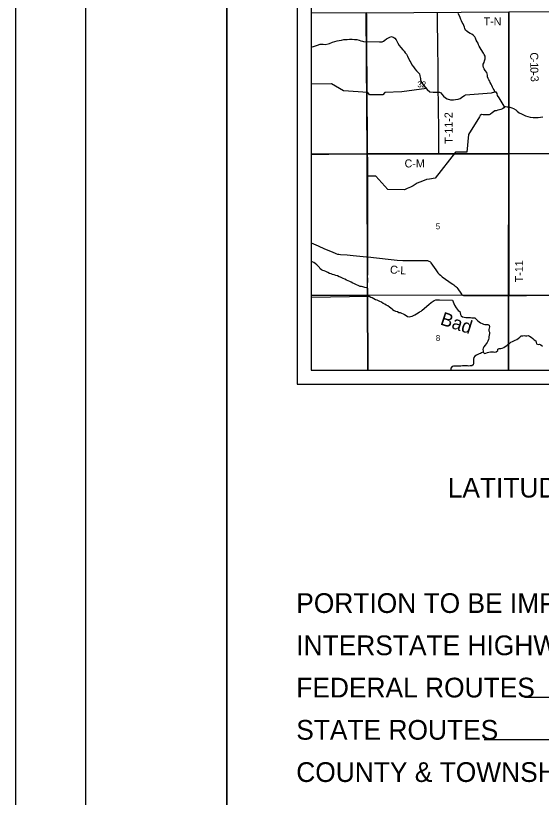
# Model space of a CAD drawing. Extents: x 0 to 34, y 0 to 22.
# Drawn here: x 0 to 3.74, y 11.07 to 16.62 of the extents above; entities that cross this region are included whole.
import ezdxf

# ---------------------------------------------------------------- set-up
doc = ezdxf.new("R2010")
doc.units = 0
for name, color, linetype in [('Default', 7, 'Continuous'), ('GM_X_County_Road', 7, 'Continuous'), ('GM_X_County_Road_Text', 7, 'Continuous'), ('GM_X_Minor_River', 7, 'Continuous'), ('GM_X_Minor_River_Text', 7, 'Continuous'), ('GM_X_Section', 7, 'Continuous'), ('GM_X_Section_Text', 7, 'Continuous'), ('GM_X_Township_Road', 7, 'Continuous'), ('GM_X_Township_Road_Text', 7, 'Continuous'), ('SH_Border', 7, 'Continuous'), ('SH_Cut_Line', 7, 'Continuous'), ('SH_Data', 7, 'Continuous'), ('SH_Text', 7, 'Continuous')]:
    doc.layers.add(name, color=color, linetype=linetype)

msp = doc.modelspace()

# ---------------------------------------------------------------- linework, layer by layer
at = {"layer": 'Default'}
for points in [[(2.1, 16.6364), (2.1, 15.6339), (2.4995, 15.6374), (2.4922, 16.6384)], [(2.1, 15.6339), (2.1, 14.6306), (2.5018, 14.6334), (2.4995, 15.6374)], [(2.1, 14.6306), (2.1, 14.1), (2.5043, 14.1), (2.5018, 14.6334)], [(2.5043, 14.1), (3.5024, 14.1), (3.5022, 14.6297), (2.5018, 14.6334)], [(3.5024, 14.1), (4.5087, 14.1), (4.5085, 14.6335), (3.5022, 14.6297)]]:
    msp.add_lwpolyline(points, close=True, dxfattribs=at)
msp.add_lwpolyline([(2.1, 16.6348), (2.1, 14.1), (7.5225, 14.1), (7.5244, 14.8701), (7.5216, 15.6399), (7.5206, 15.6813), (7.5192, 15.8554), (7.5184, 15.927), (7.5171, 16.0545), (7.5165, 16.1851), (7.5145, 16.4463), (7.5138, 16.5271), (7.5134, 16.6254)], dxfattribs=at)
at = {"layer": 'GM_X_County_Road'}
for points in [[(2.5018, 15.6365), (2.5014, 15.6639), (2.501, 15.7044), (2.501, 15.7417), (2.5006, 15.8101), (2.4991, 15.9935), (2.4985, 16.1303), (2.4979, 16.1769), (2.4966, 16.3417), (2.4965, 16.4039), (2.4959, 16.4629), (2.4958, 16.5096), (2.4953, 16.5562), (2.495, 16.6277), (2.4948, 16.6366)], [(2.1, 15.6332), (2.1688, 15.6336), (2.2248, 15.6343), (2.3211, 15.6353), (2.433, 15.6357), (2.4828, 15.636), (2.5018, 15.6365)], [(2.5018, 15.6365), (2.517, 15.6369), (2.6538, 15.6376), (2.6911, 15.6376), (2.8621, 15.6383), (3.0086, 15.639)], [(2.5029, 14.9045), (2.503, 14.9093), (2.5029, 14.9373), (2.503, 15.0526), (2.5029, 15.0985), (2.5029, 15.195), (2.5033, 15.2482), (2.5032, 15.294), (2.5032, 15.3313), (2.5032, 15.4494), (2.5029, 15.4992), (2.5029, 15.5209), (2.5024, 15.5956), (2.5018, 15.6329), (2.5018, 15.6365)], [(3.0086, 15.639), (3.0206, 15.639), (3.0952, 15.6389), (3.2383, 15.6388), (3.316, 15.6383), (3.3253, 15.6385), (3.3284, 15.6389), (3.3564, 15.639), (3.5073, 15.6383)], [(3.5073, 15.6383), (3.515, 15.6382), (3.5989, 15.6388), (3.6297, 15.6388), (3.6794, 15.639), (3.7261, 15.639), (3.7634, 15.6393), (3.8007, 15.6393), (3.8287, 15.6395), (3.8908, 15.6397), (3.9188, 15.6396), (3.9655, 15.6399), (4.0059, 15.6398), (4.0081, 15.6399)], [(2.1, 15.0042), (2.1494, 14.9828), (2.1951, 14.9631), (2.2493, 14.9397), (2.2752, 14.9288), (2.2871, 14.9249), (2.2962, 14.9229), (2.3086, 14.9213), (2.3551, 14.9185), (2.3983, 14.9157), (2.4941, 14.9055), (2.5029, 14.9045)], [(2.505, 14.1), (2.505, 14.1041), (2.5049, 14.1259), (2.5049, 14.1756), (2.5043, 14.2471), (2.5042, 14.3), (2.5039, 14.3124), (2.5036, 14.3279), (2.5039, 14.359), (2.5039, 14.3715), (2.503, 14.3905), (2.5025, 14.5109), (2.5016, 14.586), (2.5016, 14.6637), (2.5016, 14.6888), (2.5023, 14.7507), (2.5019, 14.7634), (2.5021, 14.7853), (2.5021, 14.8502), (2.5023, 14.8751), (2.5029, 14.9045)], [(2.5029, 14.9045), (2.6486, 14.8884), (2.7105, 14.8821), (2.7508, 14.879), (2.7757, 14.8784), (2.8303, 14.8792), (2.917, 14.8794), (2.9262, 14.8787), (2.9321, 14.8774), (2.9377, 14.875), (2.9428, 14.8719), (2.9474, 14.8679), (2.9514, 14.8633), (2.987, 14.8124), (3.0017, 14.7923), (3.0099, 14.7828), (3.0189, 14.7741), (3.031, 14.7643), (3.1019, 14.7144), (3.1067, 14.7102), (3.1141, 14.7052), (3.1214, 14.7002), (3.1284, 14.6942), (3.1348, 14.6875), (3.1423, 14.6777), (3.1631, 14.6467), (3.1691, 14.6394), (3.174, 14.6353), (3.1768, 14.6337), (3.1797, 14.6324), (3.1829, 14.6316), (3.1892, 14.6309), (3.2328, 14.6312), (3.3197, 14.6312), (3.4595, 14.6303), (3.493, 14.6304), (3.5083, 14.6304)], [(3.5083, 14.6304), (3.5237, 14.6305), (3.531, 14.6306), (3.6305, 14.6314), (3.9195, 14.634), (3.9471, 14.6339)]]:
    msp.add_lwpolyline(points, dxfattribs=at)
at = {"layer": 'GM_X_Minor_River'}
msp.add_line((2.1, 14.6182), (2.5092, 14.6252), dxfattribs=at)
for points in [[(3.4059, 16.0777), (3.3999, 16.0902), (3.3944, 16.1002), (3.3895, 16.1108), (3.3844, 16.1219), (3.3792, 16.1322), (3.3728, 16.1421), (3.3692, 16.1516), (3.3625, 16.1619), (3.3576, 16.1715), (3.354, 16.1829), (3.353, 16.1939), (3.3508, 16.2042), (3.3482, 16.2137), (3.3378, 16.2282), (3.3288, 16.2401), (3.3248, 16.2504), (3.3226, 16.2618), (3.3239, 16.2731), (3.3293, 16.2856), (3.3329, 16.2977), (3.3372, 16.3098), (3.3365, 16.3193), (3.3367, 16.3292), (3.3292, 16.3421), (3.324, 16.3524), (3.3084, 16.3769), (3.3017, 16.3891), (3.2954, 16.3998), (3.2891, 16.4108), (3.2861, 16.4219), (3.2798, 16.4322), (3.2727, 16.444), (3.2672, 16.4566), (3.2643, 16.4669), (3.2515, 16.4784), (3.2418, 16.4872), (3.2308, 16.4915), (3.2191, 16.4973), (3.2082, 16.5054), (3.1977, 16.515), (3.1918, 16.5253), (3.19, 16.5351), (3.1856, 16.5473), (3.1808, 16.5584), (3.1741, 16.5698), (3.1697, 16.5809), (3.1641, 16.5908), (3.156, 16.6118), (3.1456, 16.6323)], [(2.1, 16.3947), (2.116, 16.3985), (2.1449, 16.4089), (2.1644, 16.4163), (2.1852, 16.4149), (2.2007, 16.4129), (2.2209, 16.4168), (2.2315, 16.4201), (2.2521, 16.4291), (2.2688, 16.4334), (2.2844, 16.4378), (2.3003, 16.4403), (2.3163, 16.4447), (2.3334, 16.4472), (2.3554, 16.4493), (2.3732, 16.4506), (2.3911, 16.4508), (2.4092, 16.4487), (2.4248, 16.4475), (2.441, 16.4439), (2.4524, 16.4392), (2.4641, 16.4368), (2.472, 16.4329), (2.5861, 16.4322), (2.6039, 16.4324), (2.615, 16.4368), (2.6234, 16.4428), (2.636, 16.4526), (2.6501, 16.4604), (2.6592, 16.4652), (2.6707, 16.4693), (2.6873, 16.4631), (2.6944, 16.4566), (2.7034, 16.4451), (2.7164, 16.4226), (2.7264, 16.4065), (2.7376, 16.3909), (2.7515, 16.3752), (2.7605, 16.3648), (2.7679, 16.3541), (2.7784, 16.3442), (2.7847, 16.3308), (2.8021, 16.2954), (2.8085, 16.2854), (2.8166, 16.2694), (2.8271, 16.2537), (2.8364, 16.2404), (2.8495, 16.2262), (2.8619, 16.2151), (2.8693, 16.2036), (2.8738, 16.1907), (2.8777, 16.1713), (2.878, 16.1618), (2.8828, 16.1496), (2.8872, 16.1393), (2.9257, 16.0926), (2.9434, 16.0773), (2.9668, 16.0744), (2.9763, 16.0743), (2.9896, 16.0746), (3.0017, 16.0737), (3.0116, 16.0732), (3.0221, 16.0701), (3.0296, 16.0601), (3.0408, 16.0463), (3.054, 16.0341), (3.0664, 16.0264), (3.0913, 16.0204), (3.1122, 16.0202)], [(2.92, 16.0996), (2.7447, 16.0762), (2.6245, 16.0721), (2.6106, 16.0548), (2.5159, 16.0557), (2.502, 16.0725), (2.3297, 16.0837), (2.2457, 16.1328), (2.1, 16.1315)], [(3.1122, 16.0202), (3.1258, 16.0227), (3.1445, 16.0252), (3.1589, 16.0289), (3.1788, 16.0438), (3.1891, 16.0498), (3.1948, 16.0532), (3.1979, 16.0543), (3.383, 16.0699), (3.4059, 16.0777), (3.4119, 16.0772), (3.419, 16.0654), (3.4222, 16.0502), (3.4349, 16.0337), (3.4691, 15.975), (3.482, 15.9729), (3.4934, 15.9713), (3.5062, 15.9693), (3.5259, 15.9638), (3.5376, 15.9595), (3.5538, 15.9495), (3.5639, 15.9391), (3.5778, 15.9276), (3.5948, 15.9198), (3.6095, 15.9144), (3.6234, 15.9063), (3.6397, 15.9008), (3.6578, 15.8968), (3.6771, 15.894), (3.6873, 15.8939), (3.7135, 15.8936), (3.7302, 15.8965), (3.7462, 15.899)], [(3.4771, 15.9737), (3.469, 15.964), (3.4595, 15.9565), (3.4492, 15.9513), (3.4381, 15.9487), (3.4264, 15.9465), (3.4149, 15.9425), (3.4054, 15.9407), (3.3959, 15.9336), (3.3856, 15.9265), (3.3753, 15.9186), (3.3653, 15.9126), (3.3555, 15.9131), (3.3452, 15.9128), (3.3346, 15.9137), (3.3229, 15.9145), (3.3119, 15.915), (3.3024, 15.9087), (3.2966, 15.8989), (3.2961, 15.898)], [(3.2961, 15.898), (3.219, 15.774), (3.2077, 15.6489), (3.1269, 15.6478), (2.9819, 15.4648), (2.9405, 15.4576), (2.9193, 15.4541), (2.8919, 15.4426), (2.8724, 15.4344), (2.8549, 15.4278), (2.8263, 15.4087), (2.8068, 15.4005), (2.7836, 15.3894), (2.7642, 15.3801), (2.6452, 15.3835), (2.5602, 15.4785), (2.501, 15.4768)], [(2.5031, 14.6833), (2.4932, 14.6857), (2.4811, 14.6877), (2.4687, 14.6916), (2.4588, 14.694), (2.449, 14.6952), (2.4392, 14.6999), (2.4173, 14.7096), (2.4075, 14.7139), (2.3954, 14.7181), (2.3849, 14.7247), (2.3743, 14.7294), (2.3645, 14.734), (2.3521, 14.7394), (2.3389, 14.7475), (2.3287, 14.7522), (2.3189, 14.7561), (2.3087, 14.7607), (2.2989, 14.7639), (2.2883, 14.7693), (2.2755, 14.7732), (2.2634, 14.7764), (2.2524, 14.7799), (2.2422, 14.7834), (2.2317, 14.7869), (2.2185, 14.7939), (2.2049, 14.8012), (2.1936, 14.8051), (2.1838, 14.8079), (2.1739, 14.8122), (2.1642, 14.8195), (2.1593, 14.829), (2.1504, 14.8386), (2.1395, 14.8478), (2.129, 14.857), (2.1188, 14.8643), (2.1083, 14.8701), (2.1, 14.8715)], [(2.504, 14.629), (2.5031, 14.6833)], [(2.6787, 14.5322), (2.6664, 14.5402), (2.6566, 14.5478), (2.6453, 14.5574), (2.6344, 14.5629), (2.6246, 14.569), (2.6118, 14.5745), (2.5994, 14.5826), (2.5888, 14.5884), (2.5786, 14.5919), (2.5684, 14.5965), (2.5582, 14.6008), (2.5447, 14.6066), (2.5337, 14.6132), (2.5235, 14.6167), (2.5137, 14.6225), (2.504, 14.6283), (2.504, 14.629)], [(2.8903, 14.5274), (2.9377, 14.5675), (2.9542, 14.5798), (2.9748, 14.5948), (2.987, 14.5992), (3.0128, 14.6009), (3.1052, 14.5977), (3.1192, 14.5611), (3.13, 14.5424), (3.146, 14.524)], [(2.6787, 14.5322), (2.6907, 14.5235), (2.7008, 14.5199), (2.7129, 14.5162), (2.7234, 14.5107), (2.7332, 14.5097), (2.7429, 14.5045), (2.7539, 14.5013), (2.7647, 14.4953), (2.7748, 14.4894), (2.786, 14.4816), (2.7966, 14.4794), (2.8069, 14.4811), (2.818, 14.4843), (2.8276, 14.4894), (2.8383, 14.4929), (2.8495, 14.4999), (2.8602, 14.5069), (2.8714, 14.5146), (2.8822, 14.5204), (2.8903, 14.5274)], [(3.146, 14.524), (3.1564, 14.5173), (3.1604, 14.507), (3.1628, 14.4963), (3.1659, 14.4856), (3.1768, 14.4782), (3.1881, 14.4775), (3.1998, 14.475), (3.2108, 14.4744), (3.2207, 14.4734), (3.2317, 14.4739), (3.2423, 14.4725), (3.2521, 14.4731), (3.2631, 14.4721), (3.2731, 14.4623), (3.2828, 14.4526), (3.2939, 14.444), (3.3048, 14.4366), (3.3145, 14.431), (3.3243, 14.427), (3.3348, 14.4249), (3.3443, 14.4251), (3.3553, 14.4237), (3.3654, 14.4193), (3.3686, 14.409), (3.3653, 14.3988), (3.3636, 14.389), (3.3637, 14.3795), (3.3669, 14.3699), (3.3678, 14.36), (3.366, 14.3483), (3.3635, 14.3373), (3.3621, 14.3275), (3.3604, 14.3177), (3.3567, 14.3075), (3.3519, 14.297), (3.3434, 14.2873), (3.3363, 14.2768), (3.3269, 14.2668), (3.3218, 14.257), (3.3204, 14.2472), (3.3232, 14.2376), (3.3226, 14.2274), (3.3323, 14.2196), (3.3429, 14.2213), (3.3525, 14.2252), (3.3639, 14.2272), (3.3742, 14.2297), (3.3837, 14.2298), (3.3952, 14.2311), (3.4054, 14.2294), (3.4156, 14.231), (3.4269, 14.2403), (3.4267, 14.2501), (3.437, 14.2537), (3.4488, 14.2546), (3.4587, 14.2563), (3.4691, 14.2621), (3.4787, 14.2683), (3.4899, 14.2764), (3.5, 14.2842), (3.51, 14.29), (3.5205, 14.3001), (3.5301, 14.3048), (3.54, 14.3091), (3.5512, 14.3146), (3.5626, 14.3185), (3.5726, 14.3243), (3.5835, 14.3355), (3.594, 14.3432), (3.6035, 14.3453), (3.6134, 14.3462), (3.6236, 14.3445), (3.6338, 14.345), (3.6433, 14.3459), (3.6531, 14.3427), (3.6636, 14.3348), (3.6751, 14.3255), (3.6855, 14.3165), (3.696, 14.3083), (3.6991, 14.2976), (3.7023, 14.2877), (3.714, 14.2836), (3.7235, 14.2845), (3.7336, 14.2801), (3.744, 14.2712)], [(3.3226, 14.2274), (3.3112, 14.2235), (3.3042, 14.2195), (3.2943, 14.2163), (3.2839, 14.2116), (3.2743, 14.2068), (3.2643, 14.2002), (3.2564, 14.1894), (3.2539, 14.1784), (3.2529, 14.1686), (3.2542, 14.1587), (3.2543, 14.1477), (3.2526, 14.1379), (3.2425, 14.1312), (3.2312, 14.1307), (3.2205, 14.1298), (3.2103, 14.1308), (3.1955, 14.1319), (3.1856, 14.131), (3.1754, 14.1301), (3.1647, 14.1299), (3.1552, 14.129), (3.1453, 14.1285), (3.1355, 14.1283), (3.1237, 14.1293), (3.1124, 14.1296), (3.1028, 14.1268), (3.0938, 14.1156), (3.0928, 14.1031), (3.0932, 14.1)]]:
    msp.add_lwpolyline(points, dxfattribs=at)
at = {"layer": 'GM_X_Section'}
for points in [[(2.4922, 16.6384), (3.5053, 16.6448), (3.5041, 15.6366), (2.4995, 15.6374)], [(3.5053, 16.6448), (4.5021, 16.6472), (4.5104, 15.6416), (3.5041, 15.6366)], [(2.4995, 15.6374), (3.5041, 15.6366), (3.5022, 14.6297), (2.5018, 14.6334)], [(3.5041, 15.6366), (4.5104, 15.6416), (4.5085, 14.6335), (3.5022, 14.6297)]]:
    msp.add_lwpolyline(points, close=True, dxfattribs=at)
at = {"layer": 'GM_X_Township_Road'}
for points in [[(3.0086, 15.639), (3.0085, 15.646), (3.008, 15.702), (3.0076, 15.7331), (3.0076, 15.7611), (3.0069, 15.7984), (3.005, 15.9725), (3.0035, 16.1187), (3.0032, 16.1611), (3.0023, 16.2265), (3.0002, 16.4193), (2.9995, 16.4752), (2.9992, 16.5157), (2.9989, 16.553), (2.9979, 16.6405)], [(3.5083, 14.6304), (3.5083, 14.6376), (3.5078, 14.8209), (3.5078, 14.9701), (3.5071, 14.9794), (3.5076, 15.0373), (3.508, 15.0843), (3.5082, 15.1222), (3.5077, 15.1237), (3.5077, 15.1291), (3.508, 15.182), (3.5078, 15.322), (3.5075, 15.4122), (3.5079, 15.4868), (3.5074, 15.6267), (3.5073, 15.6383)]]:
    msp.add_lwpolyline(points, dxfattribs=at)
at = {"layer": 'SH_Border'}
for points in [[(0.5, 21.5), (1.5, 21.5), (1.5, 0.5), (0.5, 0.5)], [(1.5, 21.5), (33.5, 21.5), (33.5, 0.5), (1.5, 0.5)]]:
    msp.add_lwpolyline(points, close=True, dxfattribs=at)
at = {"layer": 'SH_Cut_Line'}
for points in [[(0, 0), (34, 0), (34, 22), (0, 22)], [(2.1, 20.6957), (2.1, 14.1), (8.9, 14.1), (8.9, 20.8277), (8.6079, 20.8216), (7.476, 20.811), (6.4789, 20.8005), (5.4741, 20.7803), (4.4698, 20.7584), (3.7151, 20.7343), (2.4566, 20.7022)]]:
    msp.add_lwpolyline(points, close=True, dxfattribs=at)
at = {"layer": 'SH_Data'}
for p, q in [((2, 21), (2, 14)), ((2.1, 20.9), (2.1, 14.1)), ((2.1, 14.1), (8.9, 14.1)), ((2.1, 14.1), (2.1, 14.1)), ((2, 14), (9, 14)), ((7.7, 11.7767), (3.6192, 11.7767)), ((7.7, 11.4767), (3.3288, 11.4767))]:
    msp.add_line(p, q, dxfattribs=at)

# ---------------------------------------------------------------- texts
at = {"layer": 'GM_X_County_Road_Text'}
for s, height, rotation, p in [('C', 0.0568, 270.2927, (3.6571, 16.3566)), ('1', 0.0568, 270.403, (3.6575, 16.2864)), ('-', 0.0568, 270.3251, (3.6574, 16.3099)), ('0', 0.0568, 270.7355, (3.6578, 16.2511)), ('-', 0.0568, 271.1164, (3.6582, 16.2157)), ('3', 0.0568, 274.7362, (3.6589, 16.1884)), ('C-M', 0.05682, 0, (2.7642, 15.54)), ('C', 0.0568, 353.3383, (2.6581, 14.7891)), ('L', 0.0568, 358.4796, (2.7333, 14.7812)), ('-', 0.0568, 355.0417, (2.7063, 14.7835))]:
    msp.add_text(s, height=height, rotation=rotation, dxfattribs=at).set_placement(p)
at = {"layer": 'GM_X_Minor_River_Text'}
msp.add_text('Bad', height=0.09476, rotation=341.9226, dxfattribs=at).set_placement((3.012, 14.4259))
at = {"layer": 'GM_X_Section_Text'}
for s, height, p in [('32', 0.04186, (2.855, 16.1088)), ('5', 0.0419, (2.9859, 15.101)), ('8', 0.0419, (2.9867, 14.308))]:
    msp.add_text(s, height=height, rotation=0, dxfattribs=at).set_placement(p)
at = {"layer": 'GM_X_Township_Road_Text'}
for s, rotation, p in [('T-N', 0, (3.3259, 16.5486)), ('T-11-2', 90.4959, (3.107, 15.7085)), ('T-11', 90.0083, (3.607, 14.7244))]:
    msp.add_text(s, height=0.05682, rotation=rotation, dxfattribs=at).set_placement(p)
at = {"layer": 'SH_Text'}
for s, p in [('LATITUDE:  41°42\'04"     LONGITUDE:  84°02\'13"', (3.071, 13.1959)), ('PORTION TO BE IMPROVED', (1.9944, 12.3767)), ('INTERSTATE HIGHWAY', (1.9944, 12.0767)), ('FEDERAL ROUTES', (1.9944, 11.7767)), ('STATE ROUTES', (1.9944, 11.4767)), ('COUNTY & TOWNSHIP ROADS', (1.9944, 11.1767))]:
    msp.add_text(s, height=0.14, dxfattribs=at).set_placement(p)

doc.saveas('drawing.dxf')
